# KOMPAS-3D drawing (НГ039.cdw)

Views: Спереди 1, Проекционный вид 4, Проекционный вид 5
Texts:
  Пересечение  поверхностей
  Пересечение
  поверхностей
Dimensions and other numbers on the sheet: 0; 1:1; 9; 1; 2; 3; 4; 5; 6; 7; 8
